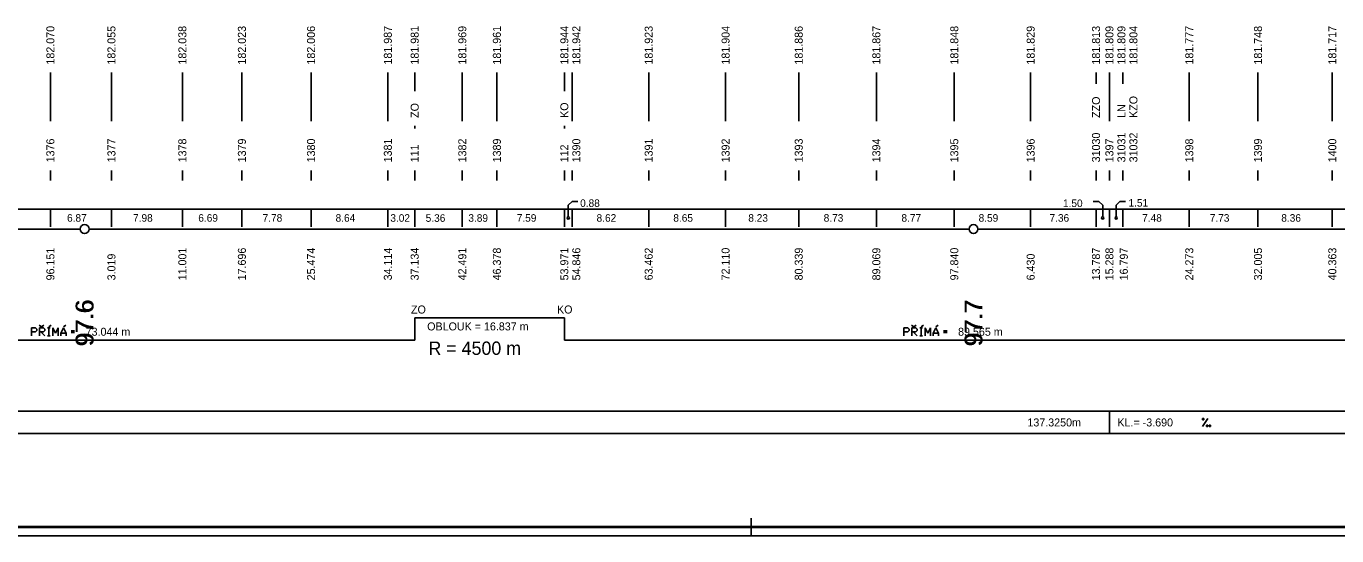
# Model space of a CAD drawing. Extents: x 0 to 10087, y -805 to 297.
# Drawn here: x 2566.9 to 2861.7, y 0 to 114.6 of the extents above; entities that cross this region are included whole.
import ezdxf

# ---------------------------------------------------------------- set-up
doc = ezdxf.new("R2010")
doc.units = 0
for name, color, linetype in [('CARKY_HODNOT', 7, 'Continuous'), ('KRIV1_CARA', 7, 'Continuous'), ('KRIV1_TEXT', 7, 'Continuous'), ('NIVELETA_CARA', 7, 'Continuous'), ('NIVELETA_TEXT', 7, 'Continuous'), ('PARAM_R', 7, 'Continuous'), ('RAM', 7, 'Continuous'), ('REZERVA', 7, 'Continuous'), ('STAN_CARA', 7, 'Continuous'), ('STAN_PAS', 7, 'Continuous'), ('STAN_TEXT', 7, 'Continuous'), ('TEXT', 7, 'Continuous'), ('TXT_C_BODU', 7, 'Continuous')]:
    doc.layers.add(name, color=color, linetype=linetype)

msp = doc.modelspace()

# ---------------------------------------------------------------- linework, layer by layer
at = {"layer": 'CARKY_HODNOT'}
for p, q in [((2572.3, 93.3), (2572.3, 104.2)), ((2586.04, 93.3), (2586.04, 104.2)), ((2602, 93.3), (2602, 104.2)), ((2615.39, 93.3), (2615.39, 104.2)), ((2630.95, 93.3), (2630.95, 104.2)), ((2648.23, 93.3), (2648.23, 104.2)), ((2654.27, 100), (2654.27, 104.2)), ((2664.98, 93.3), (2664.98, 104.2)), ((2672.76, 93.3), (2672.76, 104.2)), ((2687.94, 100), (2687.94, 104.2)), ((2689.69, 93.3), (2689.69, 104.2)), ((2706.92, 93.3), (2706.92, 104.2)), ((2724.22, 93.3), (2724.22, 104.2)), ((2740.68, 93.3), (2740.68, 104.2)), ((2758.14, 93.3), (2758.14, 104.2)), ((2775.68, 93.3), (2775.68, 104.2)), ((2792.86, 93.3), (2792.86, 104.2)), ((2807.57, 101.65), (2807.57, 104.2)), ((2810.58, 93.3), (2810.58, 104.2)), ((2810.58, 100), (2810.58, 104.2)), ((2813.59, 101.65), (2813.59, 104.2)), ((2828.55, 93.3), (2828.55, 104.2)), ((2844.01, 93.3), (2844.01, 104.2)), ((2860.73, 93.3), (2860.73, 104.2)), ((2654.27, 91.65), (2654.27, 92.2)), ((2687.94, 91.65), (2687.94, 92.2)), ((2572.3, 79.9), (2572.3, 82.2)), ((2586.04, 79.9), (2586.04, 82.2)), ((2602, 79.9), (2602, 82.2)), ((2615.39, 79.9), (2615.39, 82.2)), ((2630.95, 79.9), (2630.95, 82.2)), ((2648.23, 79.9), (2648.23, 82.2)), ((2654.27, 79.9), (2654.27, 82.2)), ((2664.98, 79.9), (2664.98, 82.2)), ((2672.76, 79.9), (2672.76, 82.2)), ((2687.94, 79.9), (2687.94, 82.2)), ((2689.69, 79.9), (2689.69, 82.2)), ((2706.92, 79.9), (2706.92, 82.2)), ((2724.22, 79.9), (2724.22, 82.2)), ((2740.68, 79.9), (2740.68, 82.2)), ((2758.14, 79.9), (2758.14, 82.2)), ((2775.68, 79.9), (2775.68, 82.2)), ((2792.86, 79.9), (2792.86, 82.2)), ((2807.57, 79.9), (2807.57, 82.2)), ((2810.58, 79.9), (2810.58, 82.2)), ((2810.58, 79.9), (2810.58, 82.2)), ((2813.59, 79.9), (2813.59, 82.2)), ((2828.55, 79.9), (2828.55, 82.2)), ((2844.01, 79.9), (2844.01, 82.2)), ((2860.73, 79.9), (2860.73, 82.2))]:
    msp.add_line(p, q, dxfattribs=at)
at = {"layer": 'KRIV1_CARA'}
for p, q in [((2654.27, 44), (2654.27, 49)), ((2654.27, 49), (2687.94, 49)), ((2687.94, 49), (2687.94, 44)), ((2508.18, 44), (2654.27, 44)), ((2687.94, 44), (2867.07, 44))]:
    msp.add_line(p, q, dxfattribs=at)
at = {"layer": 'KRIV1_TEXT'}
for p, q in [((2570.31, 47.03), (2569.8, 47.37)), ((2570.31, 47.03), (2570.82, 47.37)), ((2571.94, 47.03), (2572.45, 47.37)), ((2575.26, 47.03), (2575.77, 47.37)), ((2766.59, 47.03), (2766.08, 47.37)), ((2766.59, 47.03), (2767.1, 47.37)), ((2768.22, 47.03), (2768.73, 47.37)), ((2771.54, 47.03), (2772.05, 47.37)), ((2568.02, 45), (2568.02, 46.8)), ((2568.02, 46.8), (2568.94, 46.8)), ((2568.93, 45.9), (2568.02, 45.9)), ((2569.24, 46.2), (2568.93, 45.9)), ((2568.94, 46.8), (2569.24, 46.49)), ((2569.24, 46.49), (2569.24, 46.2)), ((2569.82, 45), (2569.82, 46.8)), ((2569.82, 46.8), (2570.73, 46.8)), ((2570.73, 45.9), (2569.82, 45.9)), ((2570.12, 45.9), (2571.03, 45)), ((2570.73, 46.8), (2571.03, 46.51)), ((2571.03, 46.2), (2570.73, 45.9)), ((2571.03, 46.51), (2571.03, 46.2)), ((2571.66, 46.79), (2572.23, 46.79)), ((2571.66, 45), (2572.23, 45)), ((2571.95, 45), (2571.95, 46.79)), ((2572.83, 45), (2572.83, 46.79)), ((2572.83, 46.79), (2573.45, 45.6)), ((2573.45, 45.6), (2574.03, 46.79)), ((2574.03, 46.79), (2574.03, 45)), ((2575.24, 46.81), (2574.63, 45.6)), ((2574.63, 45), (2574.63, 45.6)), ((2574.63, 45.6), (2575.83, 45.6)), ((2575.83, 45.6), (2575.24, 46.81)), ((2575.83, 45.6), (2575.83, 45)), ((2576.95, 46.07), (2577.76, 46.07)), ((2576.95, 45.75), (2577.76, 45.75)), ((2764.3, 45), (2764.3, 46.8)), ((2764.3, 46.8), (2765.22, 46.8)), ((2765.21, 45.9), (2764.3, 45.9)), ((2765.52, 46.2), (2765.21, 45.9)), ((2765.22, 46.8), (2765.52, 46.49)), ((2765.52, 46.49), (2765.52, 46.2)), ((2766.1, 45), (2766.1, 46.8)), ((2766.1, 46.8), (2767.01, 46.8)), ((2767.01, 45.9), (2766.1, 45.9)), ((2766.41, 45.9), (2767.31, 45)), ((2767.01, 46.8), (2767.31, 46.51)), ((2767.31, 46.2), (2767.01, 45.9)), ((2767.31, 46.51), (2767.31, 46.2)), ((2767.95, 46.79), (2768.51, 46.79)), ((2767.95, 45), (2768.51, 45)), ((2768.23, 45), (2768.23, 46.79)), ((2769.12, 45), (2769.12, 46.79)), ((2769.12, 46.79), (2769.73, 45.6)), ((2769.73, 45.6), (2770.31, 46.79)), ((2770.31, 46.79), (2770.31, 45)), ((2771.52, 46.81), (2770.92, 45.6)), ((2770.92, 45), (2770.92, 45.6)), ((2770.92, 45.6), (2772.11, 45.6)), ((2772.11, 45.6), (2771.52, 46.81)), ((2772.11, 45.6), (2772.11, 45)), ((2773.23, 46.07), (2774.05, 46.07)), ((2773.23, 45.75), (2774.05, 45.75))]:
    msp.add_line(p, q, dxfattribs=at)
at = {"layer": 'NIVELETA_CARA'}
for p, q in [((500, 28), (8321.33, 28)), ((2810.58, 23), (2810.58, 28)), ((500, 23), (8321.33, 23))]:
    msp.add_line(p, q, dxfattribs=at)
at = {"layer": 'NIVELETA_TEXT'}
for p, q in [((2831.54, 24.6), (2832.73, 26.4)), ((2831.54, 26.4), (2831.54, 26.1)), ((2831.83, 26.4), (2831.54, 26.4)), ((2831.54, 26.4), (2831.54, 26.39)), ((2831.54, 26.1), (2831.83, 26.1)), ((2831.83, 26.1), (2831.83, 26.4)), ((2832.45, 24.9), (2832.45, 24.6)), ((2832.74, 24.9), (2832.45, 24.9)), ((2832.45, 24.9), (2832.45, 24.89)), ((2832.45, 24.6), (2832.74, 24.6)), ((2832.74, 24.6), (2832.74, 24.9)), ((2833.06, 24.9), (2833.06, 24.6)), ((2833.36, 24.9), (2833.06, 24.9)), ((2833.06, 24.9), (2833.06, 24.89)), ((2833.06, 24.6), (2833.36, 24.6)), ((2833.36, 24.6), (2833.36, 24.9))]:
    msp.add_line(p, q, dxfattribs=at)
at = {"layer": 'RAM'}
for p, q in [((2730, 0), (2730, 4)), ((0, 0), (8636.33, 0)), ((2, 2.1), (8634.33, 2.1)), ((2, 2), (8634.33, 2)), ((2, 1.9), (8634.33, 1.9))]:
    msp.add_line(p, q, dxfattribs=at)
at = {"layer": 'REZERVA'}
for centre in [(2580, 69), (2780, 69)]:
    msp.add_circle(centre, 1, dxfattribs=at)
at = {"layer": 'STAN_CARA'}
for p, q in [((2381, 69), (2579, 69)), ((2581, 69), (2779, 69)), ((2781, 69), (2979, 69))]:
    msp.add_line(p, q, dxfattribs=at)
at = {"layer": 'STAN_PAS'}
for p, q in [((2688.82, 74.35), (2689.67, 75.2)), ((2688.82, 71.75), (2688.82, 74.35)), ((2689.67, 75.2), (2690.94, 75.2)), ((2808.22, 75.2), (2806.95, 75.2)), ((2809.07, 74.35), (2808.22, 75.2)), ((2809.07, 71.75), (2809.07, 74.35)), ((2812.09, 74.35), (2812.94, 75.2)), ((2812.09, 71.75), (2812.09, 74.35)), ((2812.94, 75.2), (2814.21, 75.2)), ((300, 73.5), (8321.33, 73.5)), ((2572.3, 69.5), (2572.3, 73.5)), ((2586.04, 69.5), (2586.04, 73.5)), ((2602, 69.5), (2602, 73.5)), ((2615.39, 69.5), (2615.39, 73.5)), ((2630.95, 69.5), (2630.95, 73.5)), ((2648.23, 69.5), (2648.23, 73.5)), ((2654.27, 69.5), (2654.27, 73.5)), ((2664.98, 69.5), (2664.98, 73.5)), ((2672.76, 69.5), (2672.76, 73.5)), ((2687.94, 69.5), (2687.94, 73.5)), ((2689.69, 69.5), (2689.69, 73.5)), ((2706.92, 69.5), (2706.92, 73.5)), ((2724.22, 69.5), (2724.22, 73.5)), ((2740.68, 69.5), (2740.68, 73.5)), ((2758.14, 69.5), (2758.14, 73.5)), ((2775.68, 69.5), (2775.68, 73.5)), ((2792.86, 69.5), (2792.86, 73.5)), ((2807.57, 69.5), (2807.57, 73.5)), ((2810.58, 69.5), (2810.58, 73.5)), ((2810.58, 69.5), (2810.58, 73.5)), ((2813.59, 69.5), (2813.59, 73.5)), ((2828.55, 69.5), (2828.55, 73.5)), ((2844.01, 69.5), (2844.01, 73.5)), ((2860.73, 69.5), (2860.73, 73.5))]:
    msp.add_line(p, q, dxfattribs=at)
for centre in [(2688.82, 71.5), (2809.07, 71.5), (2812.09, 71.5)]:
    msp.add_circle(centre, 0.25, dxfattribs=at)

# ---------------------------------------------------------------- texts
at = {"layer": 'KRIV1_TEXT'}
for s, p in [('ZO', (2653.44, 50)), ('KO', (2686.29, 50)), ('OBLOUK = 16.837 m', (2657.08, 46.2)), (' 73.044 m', (2579.57, 45)), (' 89.565 m', (2775.86, 45))]:
    msp.add_text(s, height=1.8, dxfattribs=at).set_placement(p)
at = {"layer": 'NIVELETA_TEXT'}
for s, p in [('137.3250m', (2792.13, 24.6)), ('KL.= -3.690', (2812.38, 24.6))]:
    msp.add_text(s, height=1.8, dxfattribs=at).set_placement(p)
at = {"layer": 'PARAM_R'}
msp.add_text('R = 4500 m', height=3, dxfattribs=at).set_placement((2657.36, 40.7))
at = {"layer": 'STAN_TEXT'}
for s, p in [('0.88', (2691.5, 73.98)), ('1.50', (2800.13, 73.95)), ('1.51', (2814.87, 74.04)), ('6.87', (2576.05, 70.65)), ('7.98', (2590.9, 70.65)), ('6.69', (2605.58, 70.65)), ('7.78', (2620.05, 70.65)), ('8.64', (2636.47, 70.65)), ('3.02', (2648.79, 70.64)), ('5.36', (2656.74, 70.63)), ('3.89', (2666.34, 70.64)), ('7.59', (2677.23, 70.65)), ('8.62', (2695.19, 70.65)), ('8.65', (2712.46, 70.65)), ('8.23', (2729.33, 70.65)), ('8.73', (2746.29, 70.65)), ('8.77', (2763.79, 70.65)), ('8.59', (2781.15, 70.65)), ('7.36', (2797.1, 70.65)), ('7.48', (2817.95, 70.65)), ('7.73', (2833.16, 70.65)), ('8.36', (2849.25, 70.65))]:
    msp.add_text(s, height=1.7, dxfattribs=at).set_placement(p)
for s, height, p in [('96.151', 1.8, (2573.2, 57.45)), ('3.019', 1.8, (2586.94, 57.45)), ('11.001', 1.8, (2602.9, 57.45)), ('17.696', 1.8, (2616.29, 57.45)), ('25.474', 1.8, (2631.85, 57.45)), ('34.114', 1.8, (2649.13, 57.45)), ('37.134', 1.8, (2655.17, 57.45)), ('42.491', 1.8, (2665.88, 57.45)), ('46.378', 1.8, (2673.66, 57.45)), ('53.971', 1.8, (2688.84, 57.45)), ('54.846', 1.8, (2691.54, 57.45)), ('63.462', 1.8, (2707.82, 57.45)), ('72.110', 1.8, (2725.12, 57.45)), ('80.339', 1.8, (2741.58, 57.45)), ('89.069', 1.8, (2759.04, 57.45)), ('97.840', 1.8, (2776.58, 57.45)), ('6.430', 1.8, (2793.76, 57.45)), ('13.787', 1.8, (2808.47, 57.45)), ('15.288', 1.8, (2811.48, 57.45)), ('16.797', 1.8, (2814.72, 57.45)), ('24.273', 1.8, (2829.45, 57.45)), ('32.005', 1.8, (2844.91, 57.45)), ('40.363', 1.8, (2861.63, 57.45)), ('    97.6', 4, (2582, 36.84)), ('    97.6', 4, (2582, 36.74)), ('    97.6', 4, (2582, 36.64)), ('    97.7', 4, (2782, 36.84)), ('    97.7', 4, (2782, 36.74)), ('    97.7', 4, (2782, 36.64))]:
    msp.add_text(s, height=height, rotation=90, dxfattribs=at).set_placement(p)
at = {"layer": 'TEXT'}
for s, p in [('182.070', (2573.2, 106)), ('182.055', (2586.94, 106)), ('182.038', (2602.9, 106)), ('182.023', (2616.29, 106)), ('182.006', (2631.85, 106)), ('181.987', (2649.13, 106)), ('181.981', (2655.17, 106)), ('181.969', (2665.88, 106)), ('181.961', (2673.66, 106)), ('181.944', (2688.84, 106)), ('181.942', (2691.54, 106)), ('181.923', (2707.82, 106)), ('181.904', (2725.12, 106)), ('181.886', (2741.58, 106)), ('181.867', (2759.04, 106)), ('181.848', (2776.58, 106)), ('181.829', (2793.76, 106)), ('181.813', (2808.47, 106)), ('181.809', (2811.48, 106)), ('181.809', (2814.18, 106)), ('181.804', (2816.88, 106)), ('181.777', (2829.45, 106)), ('181.748', (2844.91, 106)), ('181.717', (2861.63, 106)), ('KO', (2688.84, 94)), ('ZZO', (2808.47, 94)), ('KZO', (2816.88, 94)), ('ZO', (2655.17, 94)), ('LN', (2814.18, 94))]:
    msp.add_text(s, height=1.8, rotation=90, dxfattribs=at).set_placement(p)
at = {"layer": 'TXT_C_BODU'}
for s, p in [('1376', (2573.2, 84)), ('1377', (2586.94, 84)), ('1378', (2602.9, 84)), ('1379', (2616.29, 84)), ('1380', (2631.85, 84)), ('1381', (2649.13, 84)), ('1382', (2665.88, 84)), ('1389', (2673.66, 84)), ('1390', (2691.54, 84)), ('1391', (2707.82, 84)), ('1392', (2725.12, 84)), ('1393', (2741.58, 84)), ('1394', (2759.04, 84)), ('1395', (2776.58, 84)), ('1396', (2793.76, 84)), ('31030', (2808.47, 84)), ('1397', (2811.48, 84)), ('31031', (2814.18, 84)), ('31032', (2816.88, 84)), ('1398', (2829.45, 84)), ('1399', (2844.91, 84)), ('1400', (2861.63, 84)), ('111', (2655.17, 84)), ('112', (2688.84, 84))]:
    msp.add_text(s, height=1.8, rotation=90, dxfattribs=at).set_placement(p)

doc.saveas('drawing.dxf')
